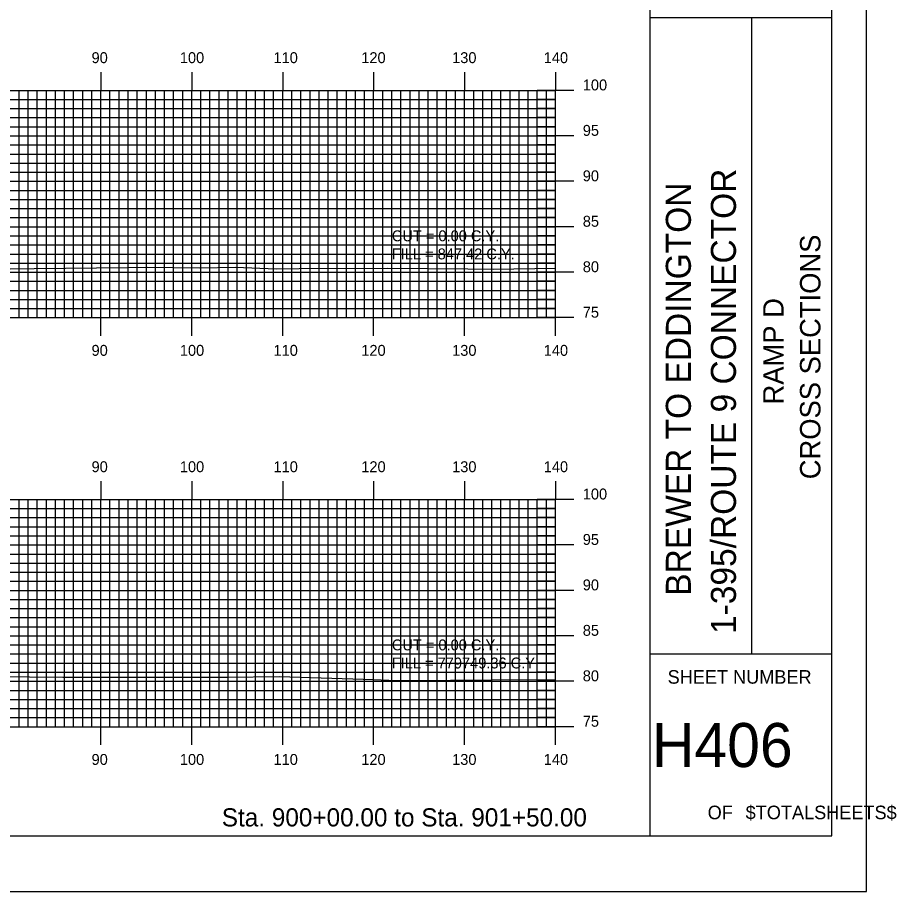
# Model space of a CAD drawing. Extents: x 856323 to 856666, y 364765 to 364985.
# Drawn here: x 856569.6 to 856666.3, y 364765.2 to 364861.3 of the extents above; entities that cross this region are included whole.
import ezdxf

# ---------------------------------------------------------------- set-up
doc = ezdxf.new("R2010")
doc.units = 0
for name, color, linetype in [('BORDER', 7, 'Continuous'), ('D_Text_Standard', 7, 'Continuous'), ('H_V ANNOTATION', 7, 'Continuous'), ('MAJOR', 7, 'Continuous'), ('MINOR', 7, 'Continuous'), ('PLOT BOUNDARY', 7, 'Continuous'), ('S_Roadway_Centerline', 7, 'Continuous')]:
    doc.layers.add(name, color=color, linetype=linetype)

msp = doc.modelspace()

# ---------------------------------------------------------------- linework, layer by layer
at = {"layer": 'BORDER'}
for p, q in [((856639.168, 364771.302), (856639.168, 364981.302)), ((856639.168, 364861.308), (856659.168, 364861.308)), ((856650.35, 364791.308), (856650.35, 364861.308)), ((856639.168, 364791.308), (856659.168, 364791.308))]:
    msp.add_line(p, q, dxfattribs=at)
msp.add_lwpolyline([(856339.168, 364771.302), (856659.168, 364771.302), (856659.168, 364981.302), (856339.168, 364981.302)], close=True, dxfattribs=at)
at = {"layer": 'MAJOR'}
for p, q in [((856578.768, 364855.306), (856578.768, 364853.302)), ((856588.768, 364855.306), (856588.768, 364853.302)), ((856598.768, 364855.306), (856598.768, 364853.302)), ((856608.768, 364855.306), (856608.768, 364853.302)), ((856618.768, 364855.306), (856618.768, 364853.302)), ((856628.768, 364855.306), (856628.768, 364853.302)), ((856348.768, 364853.302), (856628.768, 364853.302)), ((856348.768, 364853.302), (856628.768, 364853.302)), ((856578.768, 364828.302), (856578.768, 364853.302)), ((856588.768, 364828.302), (856588.768, 364853.302)), ((856598.768, 364828.302), (856598.768, 364853.302)), ((856608.768, 364828.302), (856608.768, 364853.302)), ((856618.768, 364828.302), (856618.768, 364853.302)), ((856630.772, 364853.302), (856626.764, 364853.302)), ((856628.768, 364828.302), (856628.768, 364853.302)), ((856628.768, 364828.302), (856628.768, 364853.302)), ((856348.768, 364848.302), (856628.768, 364848.302)), ((856630.772, 364848.302), (856626.764, 364848.302)), ((856348.768, 364843.302), (856628.768, 364843.302)), ((856630.772, 364843.302), (856626.764, 364843.302)), ((856348.768, 364838.302), (856628.768, 364838.302)), ((856630.772, 364838.302), (856626.764, 364838.302)), ((856348.768, 364833.302), (856628.768, 364833.302)), ((856630.772, 364833.302), (856626.764, 364833.302)), ((856348.768, 364828.302), (856628.768, 364828.302)), ((856348.768, 364828.302), (856628.768, 364828.302)), ((856578.768, 364826.298), (856578.768, 364828.302)), ((856588.768, 364826.298), (856588.768, 364828.302)), ((856598.768, 364826.298), (856598.768, 364828.302)), ((856608.768, 364826.298), (856608.768, 364828.302)), ((856618.768, 364826.298), (856618.768, 364828.302)), ((856630.772, 364828.302), (856626.764, 364828.302)), ((856628.768, 364826.298), (856628.768, 364828.302)), ((856578.768, 364810.306), (856578.768, 364808.302)), ((856588.768, 364810.306), (856588.768, 364808.302)), ((856598.768, 364810.306), (856598.768, 364808.302)), ((856608.768, 364810.306), (856608.768, 364808.302)), ((856618.768, 364810.306), (856618.768, 364808.302)), ((856628.768, 364810.306), (856628.768, 364808.302)), ((856348.768, 364808.302), (856628.768, 364808.302)), ((856348.768, 364808.302), (856628.768, 364808.302)), ((856578.768, 364783.302), (856578.768, 364808.302)), ((856588.768, 364783.302), (856588.768, 364808.302)), ((856598.768, 364783.302), (856598.768, 364808.302)), ((856608.768, 364783.302), (856608.768, 364808.302)), ((856618.768, 364783.302), (856618.768, 364808.302)), ((856630.772, 364808.302), (856626.764, 364808.302)), ((856628.768, 364783.302), (856628.768, 364808.302)), ((856628.768, 364783.302), (856628.768, 364808.302)), ((856348.768, 364803.302), (856628.768, 364803.302)), ((856630.772, 364803.302), (856626.764, 364803.302)), ((856348.768, 364798.302), (856628.768, 364798.302)), ((856630.772, 364798.302), (856626.764, 364798.302)), ((856348.768, 364793.302), (856628.768, 364793.302)), ((856630.772, 364793.302), (856626.764, 364793.302)), ((856348.768, 364788.302), (856628.768, 364788.302)), ((856630.772, 364788.302), (856626.764, 364788.302)), ((856348.768, 364783.302), (856628.768, 364783.302)), ((856348.768, 364783.302), (856628.768, 364783.302)), ((856578.768, 364781.298), (856578.768, 364783.302)), ((856588.768, 364781.298), (856588.768, 364783.302)), ((856598.768, 364781.298), (856598.768, 364783.302)), ((856608.768, 364781.298), (856608.768, 364783.302)), ((856618.768, 364781.298), (856618.768, 364783.302)), ((856630.772, 364783.302), (856626.764, 364783.302)), ((856628.768, 364781.298), (856628.768, 364783.302))]:
    msp.add_line(p, q, dxfattribs=at)
at = {"layer": 'MINOR'}
for p, q in [((856569.768, 364828.302), (856569.768, 364853.302)), ((856570.768, 364828.302), (856570.768, 364853.302)), ((856571.768, 364828.302), (856571.768, 364853.302)), ((856572.768, 364828.302), (856572.768, 364853.302)), ((856573.768, 364828.302), (856573.768, 364853.302)), ((856574.768, 364828.302), (856574.768, 364853.302)), ((856575.768, 364828.302), (856575.768, 364853.302)), ((856576.768, 364828.302), (856576.768, 364853.302)), ((856577.768, 364828.302), (856577.768, 364853.302)), ((856579.768, 364828.302), (856579.768, 364853.302)), ((856580.768, 364828.302), (856580.768, 364853.302)), ((856581.768, 364828.302), (856581.768, 364853.302)), ((856582.768, 364828.302), (856582.768, 364853.302)), ((856583.768, 364828.302), (856583.768, 364853.302)), ((856584.768, 364828.302), (856584.768, 364853.302)), ((856585.768, 364828.302), (856585.768, 364853.302)), ((856586.768, 364828.302), (856586.768, 364853.302)), ((856587.768, 364828.302), (856587.768, 364853.302)), ((856589.768, 364828.302), (856589.768, 364853.302)), ((856590.768, 364828.302), (856590.768, 364853.302)), ((856591.768, 364828.302), (856591.768, 364853.302)), ((856592.768, 364828.302), (856592.768, 364853.302)), ((856593.768, 364828.302), (856593.768, 364853.302)), ((856594.768, 364828.302), (856594.768, 364853.302)), ((856595.768, 364828.302), (856595.768, 364853.302)), ((856596.768, 364828.302), (856596.768, 364853.302)), ((856597.768, 364828.302), (856597.768, 364853.302)), ((856599.768, 364828.302), (856599.768, 364853.302)), ((856600.768, 364828.302), (856600.768, 364853.302)), ((856601.768, 364828.302), (856601.768, 364853.302)), ((856602.768, 364828.302), (856602.768, 364853.302)), ((856603.768, 364828.302), (856603.768, 364853.302)), ((856604.768, 364828.302), (856604.768, 364853.302)), ((856605.768, 364828.302), (856605.768, 364853.302)), ((856606.768, 364828.302), (856606.768, 364853.302)), ((856607.768, 364828.302), (856607.768, 364853.302)), ((856609.768, 364828.302), (856609.768, 364853.302)), ((856610.768, 364828.302), (856610.768, 364853.302)), ((856611.768, 364828.302), (856611.768, 364853.302)), ((856612.768, 364828.302), (856612.768, 364853.302)), ((856613.768, 364828.302), (856613.768, 364853.302)), ((856614.768, 364828.302), (856614.768, 364853.302)), ((856615.768, 364828.302), (856615.768, 364853.302)), ((856616.768, 364828.302), (856616.768, 364853.302)), ((856617.768, 364828.302), (856617.768, 364853.302)), ((856619.768, 364828.302), (856619.768, 364853.302)), ((856620.768, 364828.302), (856620.768, 364853.302)), ((856621.768, 364828.302), (856621.768, 364853.302)), ((856622.768, 364828.302), (856622.768, 364853.302)), ((856623.768, 364828.302), (856623.768, 364853.302)), ((856624.768, 364828.302), (856624.768, 364853.302)), ((856625.768, 364828.302), (856625.768, 364853.302)), ((856626.768, 364828.302), (856626.768, 364853.302)), ((856627.768, 364828.302), (856627.768, 364853.302)), ((856348.768, 364852.302), (856628.768, 364852.302)), ((856628.768, 364852.302), (856626.764, 364852.302)), ((856348.768, 364851.302), (856628.768, 364851.302)), ((856628.768, 364851.302), (856626.764, 364851.302)), ((856348.768, 364850.302), (856628.768, 364850.302)), ((856628.768, 364850.302), (856626.764, 364850.302)), ((856348.768, 364849.302), (856628.768, 364849.302)), ((856628.768, 364849.302), (856626.764, 364849.302)), ((856348.768, 364847.302), (856628.768, 364847.302)), ((856628.768, 364847.302), (856626.764, 364847.302)), ((856348.768, 364846.302), (856628.768, 364846.302)), ((856628.768, 364846.302), (856626.764, 364846.302)), ((856348.768, 364845.302), (856628.768, 364845.302)), ((856628.768, 364845.302), (856626.764, 364845.302)), ((856348.768, 364844.302), (856628.768, 364844.302)), ((856628.768, 364844.302), (856626.764, 364844.302)), ((856348.768, 364842.302), (856628.768, 364842.302)), ((856628.768, 364842.302), (856626.764, 364842.302)), ((856348.768, 364841.302), (856628.768, 364841.302)), ((856628.768, 364841.302), (856626.764, 364841.302)), ((856348.768, 364840.302), (856628.768, 364840.302)), ((856628.768, 364840.302), (856626.764, 364840.302)), ((856348.768, 364839.302), (856628.768, 364839.302)), ((856628.768, 364839.302), (856626.764, 364839.302)), ((856348.768, 364837.302), (856628.768, 364837.302)), ((856628.768, 364837.302), (856626.764, 364837.302)), ((856348.768, 364836.302), (856628.768, 364836.302)), ((856628.768, 364836.302), (856626.764, 364836.302)), ((856348.768, 364835.302), (856628.768, 364835.302)), ((856628.768, 364835.302), (856626.764, 364835.302)), ((856348.768, 364834.302), (856628.768, 364834.302)), ((856628.768, 364834.302), (856626.764, 364834.302)), ((856348.768, 364832.302), (856628.768, 364832.302)), ((856628.768, 364832.302), (856626.764, 364832.302)), ((856348.768, 364831.302), (856628.768, 364831.302)), ((856628.768, 364831.302), (856626.764, 364831.302)), ((856348.768, 364830.302), (856628.768, 364830.302)), ((856628.768, 364830.302), (856626.764, 364830.302)), ((856348.768, 364829.302), (856628.768, 364829.302)), ((856628.768, 364829.302), (856626.764, 364829.302)), ((856569.768, 364783.302), (856569.768, 364808.302)), ((856570.768, 364783.302), (856570.768, 364808.302)), ((856571.768, 364783.302), (856571.768, 364808.302)), ((856572.768, 364783.302), (856572.768, 364808.302)), ((856573.768, 364783.302), (856573.768, 364808.302)), ((856574.768, 364783.302), (856574.768, 364808.302)), ((856575.768, 364783.302), (856575.768, 364808.302)), ((856576.768, 364783.302), (856576.768, 364808.302)), ((856577.768, 364783.302), (856577.768, 364808.302)), ((856579.768, 364783.302), (856579.768, 364808.302)), ((856580.768, 364783.302), (856580.768, 364808.302)), ((856581.768, 364783.302), (856581.768, 364808.302)), ((856582.768, 364783.302), (856582.768, 364808.302)), ((856583.768, 364783.302), (856583.768, 364808.302)), ((856584.768, 364783.302), (856584.768, 364808.302)), ((856585.768, 364783.302), (856585.768, 364808.302)), ((856586.768, 364783.302), (856586.768, 364808.302)), ((856587.768, 364783.302), (856587.768, 364808.302)), ((856589.768, 364783.302), (856589.768, 364808.302)), ((856590.768, 364783.302), (856590.768, 364808.302)), ((856591.768, 364783.302), (856591.768, 364808.302)), ((856592.768, 364783.302), (856592.768, 364808.302)), ((856593.768, 364783.302), (856593.768, 364808.302)), ((856594.768, 364783.302), (856594.768, 364808.302)), ((856595.768, 364783.302), (856595.768, 364808.302)), ((856596.768, 364783.302), (856596.768, 364808.302)), ((856597.768, 364783.302), (856597.768, 364808.302)), ((856599.768, 364783.302), (856599.768, 364808.302)), ((856600.768, 364783.302), (856600.768, 364808.302)), ((856601.768, 364783.302), (856601.768, 364808.302)), ((856602.768, 364783.302), (856602.768, 364808.302)), ((856603.768, 364783.302), (856603.768, 364808.302)), ((856604.768, 364783.302), (856604.768, 364808.302)), ((856605.768, 364783.302), (856605.768, 364808.302)), ((856606.768, 364783.302), (856606.768, 364808.302)), ((856607.768, 364783.302), (856607.768, 364808.302)), ((856609.768, 364783.302), (856609.768, 364808.302)), ((856610.768, 364783.302), (856610.768, 364808.302)), ((856611.768, 364783.302), (856611.768, 364808.302)), ((856612.768, 364783.302), (856612.768, 364808.302)), ((856613.768, 364783.302), (856613.768, 364808.302)), ((856614.768, 364783.302), (856614.768, 364808.302)), ((856615.768, 364783.302), (856615.768, 364808.302)), ((856616.768, 364783.302), (856616.768, 364808.302)), ((856617.768, 364783.302), (856617.768, 364808.302)), ((856619.768, 364783.302), (856619.768, 364808.302)), ((856620.768, 364783.302), (856620.768, 364808.302)), ((856621.768, 364783.302), (856621.768, 364808.302)), ((856622.768, 364783.302), (856622.768, 364808.302)), ((856623.768, 364783.302), (856623.768, 364808.302)), ((856624.768, 364783.302), (856624.768, 364808.302)), ((856625.768, 364783.302), (856625.768, 364808.302)), ((856626.768, 364783.302), (856626.768, 364808.302)), ((856627.768, 364783.302), (856627.768, 364808.302)), ((856348.768, 364807.302), (856628.768, 364807.302)), ((856628.768, 364807.302), (856626.764, 364807.302)), ((856348.768, 364806.302), (856628.768, 364806.302)), ((856628.768, 364806.302), (856626.764, 364806.302)), ((856348.768, 364805.302), (856628.768, 364805.302)), ((856628.768, 364805.302), (856626.764, 364805.302)), ((856348.768, 364804.302), (856628.768, 364804.302)), ((856628.768, 364804.302), (856626.764, 364804.302)), ((856348.768, 364802.302), (856628.768, 364802.302)), ((856628.768, 364802.302), (856626.764, 364802.302)), ((856348.768, 364801.302), (856628.768, 364801.302)), ((856628.768, 364801.302), (856626.764, 364801.302)), ((856348.768, 364800.302), (856628.768, 364800.302)), ((856628.768, 364800.302), (856626.764, 364800.302)), ((856348.768, 364799.302), (856628.768, 364799.302)), ((856628.768, 364799.302), (856626.764, 364799.302)), ((856348.768, 364797.302), (856628.768, 364797.302)), ((856628.768, 364797.302), (856626.764, 364797.302)), ((856348.768, 364796.302), (856628.768, 364796.302)), ((856628.768, 364796.302), (856626.764, 364796.302)), ((856348.768, 364795.302), (856628.768, 364795.302)), ((856628.768, 364795.302), (856626.764, 364795.302)), ((856348.768, 364794.302), (856628.768, 364794.302)), ((856628.768, 364794.302), (856626.764, 364794.302)), ((856348.768, 364792.302), (856628.768, 364792.302)), ((856628.768, 364792.302), (856626.764, 364792.302)), ((856348.768, 364791.302), (856628.768, 364791.302)), ((856628.768, 364791.302), (856626.764, 364791.302)), ((856348.768, 364790.302), (856628.768, 364790.302)), ((856628.768, 364790.302), (856626.764, 364790.302)), ((856348.768, 364789.302), (856628.768, 364789.302)), ((856628.768, 364789.302), (856626.764, 364789.302)), ((856348.768, 364787.302), (856628.768, 364787.302)), ((856628.768, 364787.302), (856626.764, 364787.302)), ((856348.768, 364786.302), (856628.768, 364786.302)), ((856628.768, 364786.302), (856626.764, 364786.302)), ((856348.768, 364785.302), (856628.768, 364785.302)), ((856628.768, 364785.302), (856626.764, 364785.302)), ((856348.768, 364784.302), (856628.768, 364784.302)), ((856628.768, 364784.302), (856626.764, 364784.302))]:
    msp.add_line(p, q, dxfattribs=at)
at = {"layer": 'PLOT BOUNDARY'}
msp.add_lwpolyline([(856322.982, 364765.184), (856662.982, 364765.184), (856662.982, 364985.184), (856322.982, 364985.184)], close=True, dxfattribs=at)
at = {"layer": 'S_Roadway_Centerline'}
for points in [[(856563.443, 364833.597), (856571.424, 364833.699), (856581.738, 364833.826), (856583.918, 364833.85), (856589.656, 364833.798), (856593.581, 364833.848), (856598.05, 364833.673), (856600.59, 364833.707), (856610.246, 364833.737), (856619.109, 364833.682), (856621.909, 364833.63), (856628.768, 364833.746)], [(856467.245, 364789.883), (856481.397, 364789.741), (856490.903, 364789.576), (856496.772, 364789.408), (856503.027, 364789.391), (856512.402, 364789.138), (856516.046, 364789.126), (856526.862, 364789.385), (856535.128, 364789.259), (856545.068, 364789.082), (856550.824, 364789.019), (856554.531, 364789.035), (856563.493, 364788.873), (856574.574, 364788.764), (856575.241, 364788.768), (856576.228, 364788.745), (856592.678, 364788.737), (856598.386, 364788.819), (856608.798, 364788.494), (856611.234, 364788.396), (856612.656, 364788.381), (856621.756, 364788.461), (856628.768, 364788.505)]]:
    msp.add_lwpolyline(points, dxfattribs=at)

# ---------------------------------------------------------------- texts
at = {"layer": 'BORDER'}
for s, height, p in [('1-395/ROUTE 9 CONNECTOR', 2.75575, (856648.617, 364793.502)), ('BREWER TO EDDINGTON', 2.75575, (856643.657, 364797.711)), ('CROSS SECTIONS', 2.25, (856657.909, 364810.524)), ('RAMP D', 2.25, (856653.859, 364818.752))]:
    msp.add_text(s, height=height, rotation=90, dxfattribs=at).set_placement(p)
for s, height, p in [('SHEET NUMBER', 1.49054, (856641.099, 364788.035)), ('H406', 4.8388, (856639.379, 364778.867)), ('OF', 1.4905, (856645.502, 364773.128)), ('$TOTALSHEETS$', 1.49054, (856649.681, 364773.128))]:
    msp.add_text(s, height=height, dxfattribs=at).set_placement(p)
at = {"layer": 'D_Text_Standard'}
for s, p in [('CUT = 0.00 C.Y.', (856610.768, 364836.702)), ('FILL = 847.42 C.Y.', (856610.768, 364834.71)), ('CUT = 0.00 C.Y.', (856610.768, 364791.702)), ('FILL = 779749.36 C.Y.', (856610.768, 364789.71))]:
    msp.add_text(s, height=1.2, dxfattribs=at).set_placement(p)
at = {"layer": 'H_V ANNOTATION'}
for s, height, p in [('90', 1.2, (856577.741, 364856.302)), ('100', 1.2, (856587.452, 364856.302)), ('110', 1.2, (856597.752, 364856.302)), ('120', 1.2, (856607.409, 364856.302)), ('130', 1.2, (856617.398, 364856.302)), ('140', 1.2, (856627.473, 364856.302)), ('100', 1.2, (856631.768, 364853.302)), ('95', 1.2, (856631.768, 364848.302)), ('90', 1.2, (856631.768, 364843.302)), ('85', 1.2, (856631.768, 364838.302)), ('80', 1.2, (856631.768, 364833.302)), ('75', 1.2, (856631.768, 364828.302)), ('90', 1.2, (856577.741, 364824.102)), ('100', 1.2, (856587.452, 364824.102)), ('110', 1.2, (856597.752, 364824.102)), ('120', 1.2, (856607.409, 364824.102)), ('130', 1.2, (856617.398, 364824.102)), ('140', 1.2, (856627.473, 364824.102)), ('90', 1.2, (856577.741, 364811.302)), ('100', 1.2, (856587.452, 364811.302)), ('110', 1.2, (856597.752, 364811.302)), ('120', 1.2, (856607.409, 364811.302)), ('130', 1.2, (856617.398, 364811.302)), ('140', 1.2, (856627.473, 364811.302)), ('100', 1.2, (856631.768, 364808.302)), ('95', 1.2, (856631.768, 364803.302)), ('90', 1.2, (856631.768, 364798.302)), ('85', 1.2, (856631.768, 364793.302)), ('80', 1.2, (856631.768, 364788.302)), ('75', 1.2, (856631.768, 364783.302)), ('90', 1.2, (856577.741, 364779.102)), ('100', 1.2, (856587.452, 364779.102)), ('110', 1.2, (856597.752, 364779.102)), ('120', 1.2, (856607.409, 364779.102)), ('130', 1.2, (856617.398, 364779.102)), ('140', 1.2, (856627.473, 364779.102)), ('Sta. 900+00.00 to Sta. 901+50.00', 2.0004, (856592.065, 364772.332))]:
    msp.add_text(s, height=height, dxfattribs=at).set_placement(p)

doc.saveas('drawing.dxf')
